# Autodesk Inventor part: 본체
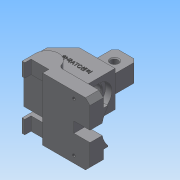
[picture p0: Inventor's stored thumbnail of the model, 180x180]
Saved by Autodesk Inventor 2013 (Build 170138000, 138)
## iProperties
Created: 2016-11
Part Number: 본체
Material: 일반
Document SubType Name: Modeling
Designer: Administrator
Density: 1 g/cm^3
Author: Administrator
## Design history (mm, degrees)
sketch "스케치3"
  geometry: L1 (-9, 18)-(-27, 0); L2 (-27, 0)-(-27, -30); L3 (-27, -30)-(10, -30); L4 (10, -30)-(10, -42); L5 (10, -42)-(63, -42); L6 (63, -42)-(63, -22); L7 (63, -22)-(31, -22); L8 (31, -22)-(31, 18); L9 (31, 18)-(-9, 18); 1 further point
  constraints: 18 end point, 7 perpendicular, 1 vertical
  dimensions: "d4" = 48 distance between parallel lines of L9 L3; "d7" = 30 distance from line of point (0, 0) L3; "d8" = 45 deg angle of L9 L1; "d9" = 18 distance from line of L1.start L2; "d10" = 63 distance from line of point (0, 0) L6; "d11" = 20 distance of L5.end L6.end; "d12" = 90 distance between parallel lines of L2 L6; "d13" = 58 distance between parallel lines of L8 L2; "d14" = 10 distance from line of point (0, 0) L4; "d15" = 60 distance between parallel lines of L5 L9
extrude "돌출1" new body sketch "스케치3" stored distance "d16" = 40; taper "d17" = 0 deg
sketch "스케치4"
  geometry: L1 (1, 48)-(26, 48); L2 (26, 48)-(26, 18); L3 (26, 18)-(1, 18); L4 (1, 18)-(1, 48); L5 (-9, 18)-(31, 18) reference; L6 (31, 18)-(31, -22) reference; L7 (63, -42)-(10, -42) reference; 2 further points
  constraints: 8 end point, 2 parallel, 1 horizontal, 1 midpoint, 1 perpendicular, 1 point on line
  dimensions: "d18" = 25 distance of L1.start L1.end; "d20" = 5 distance between parallel lines of L6 L2; "d21" = 90 distance between parallel lines of L7 L1
extrude "돌출2" join sketch "스케치4" stored distance "d22" = 20; taper "d23" = 0 deg
sketch "스케치6"
  geometry: L1 (1, 48)-(1, 18) reference; C1 r 4 at (13.5, 35); 1 further point
  constraints: 1 centre point
  dimensions: "d25" = 8 diameter of C1; "d26" = 35 vertical distance of C1.centre point (0, 0); "d27" = 12.5 distance from line of L1 C1.centre
extrude "돌출3" cut sketch "스케치6" stored distance "d28" = 20; taper "d29" = 0 deg
chamfer "모따기1" distance "d30" = 4; stored, may be unused: second distance "d31" = 2, angle "d32" = 45 deg
sketch "스케치7"
  geometry: 2 further points
  constraints: 1 coincident
hole "구멍1" sketch "스케치7" at (20, 22) diameter "d33" = 20; stored, may be unused: countersink angle "d37" = 90 deg, drill point angle "d39" = 0 deg; dims "d34" = 6, "d35" = 29, "d36" = 7, "d38" = 8
chamfer "모따기2" distance "d40" = 1; stored, may be unused: second distance "d41" = 2, angle "d42" = 45 deg
node "작업 평면1"
sketch "스케치9"
  geometry: L1 (40, 20)-(0, 20) reference; A1 r 29 centre (20, 42) between (1.106, 20) and (38.894, 20); 1 further point
  constraints: 2 point on circle, 2 point on line, 1 centre point, 1 coincident
  dimensions: "d44" = 29 radius of A1
extrude "돌출4" cut sketch "스케치9" stored distance "d45" = 20; taper "d46" = 0 deg
sketch "스케치10"
  geometry: L1 (40, 0)-(0, 0) reference; L2 (14, 20)-(26, 20); L3 (26, 20)-(26, 0); L4 (26, 0)-(14, 0); L5 (14, 0)-(14, 20); L6 (1.106, 20)-(38.894, 20) reference; A1 r 29 centre (20, 42) between (1.106, 20) and (38.894, 20) reference; 3 further points
  constraints: 8 end point, 4 midpoint, 2 parallel, 1 coincident, 1 horizontal, 1 perpendicular, 1 vertical alignment
  dimensions: "d47" = 12 distance of L2.start L2.end
extrude "돌출5" cut sketch "스케치10" distance "d49" = 18; taper "d50" = 0 deg
sketch "스케치11"
  geometry: L1 (10, -30)-(10, -42) reference; L2 (10, -42)-(63, -42) reference; L3 (63, -42)-(63, -22) reference; L4 (-10, -35)-(-10, -42); L5 (-10, -42)-(-13, -42); L6 (-13, -42)-(-13, -27); L7 (10, -42)-(63, -42); L8 (63, -42)-(63, -27); L9 (63, -27)-(13, -27); L10 (10, -42)-(10, -35); L11 (10, -35)-(-10, -35); A1 r 13 centre (0, -27) between (13, -27) and (-13, -27); 3 further points
  constraints: 16 end point, 2 horizontal alignment, 2 midpoint, 2 perpendicular, 2 point on circle, 2 point on line, 1 centre point, 1 collinear, 1 horizontal, 1 parallel, 1 tangent, 1 vertical, 1 vertical alignment
  dimensions: "d51" = 3 distance of L4.end L5.end; "d52" = 15 distance of L2.end L8.end; "d79" = 7 distance between parallel lines of L2 L11; "d80" = 20 distance of L10.end L4.start
extrude "돌출6" join sketch "스케치11" distance "d56" = 15; taper "d57" = 0 deg
fillet "모깎기1" dims "d58" = 5
chamfer "모따기3" distance "d59" = 5; stored, may be unused: second distance "d60" = 2, angle "d61" = 45 deg
sketch "스케치12"
  geometry: L1 (45.708, 0)-(45.708, -10) reference; 2 further points
  dimensions: "d62" = 27.5 vertical distance of point (-17.292, 20) point (27.708, -7.5); "d63" = 18 distance from line of L1 point (27.708, -7.5)
hole "구멍2" sketch "스케치12" at (27.708, -7.5) diameter "d64" = 3.242; stored, may be unused: countersink angle "d68" = 90 deg, drill point angle "d70" = 0 deg; dims "d65" = 15, "d66" = 29, "d67" = 7, "d69" = 8
chamfer "모따기4" distance "d71" = 1; stored, may be unused: second distance "d72" = 2, angle "d73" = 45 deg
fillet "모깎기2" dims "d74" = 3
sketch "스케치13"
  geometry: L1 (31, -19)-(31, 18) reference; L2 (31, 18)-(-9, 18) reference; 2 further points
  constraints: 1 other
  dimensions: "d75" = 25 distance from line of L1 point (6, 0); "d76" = 18 distance from line of L2 point (6, 0)
feature "엠보싱1" sketch "스케치13" dims "d4" = 48, "d7" = 30, "d8" = 45 deg, "d9" = 18, "d10" = 63, "d11" = 20, "d12" = 90, "d13" = 58, "d14" = 10, "d15" = 60, "d21" = 90, "d77" = 0.5, "d78" = 0
node "솔리드1"
mirror "대칭1"
mirror "대칭2"
other parameters: "d43" = -18, "d53" = 26
